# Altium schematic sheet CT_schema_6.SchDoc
size 274 x 160 mm
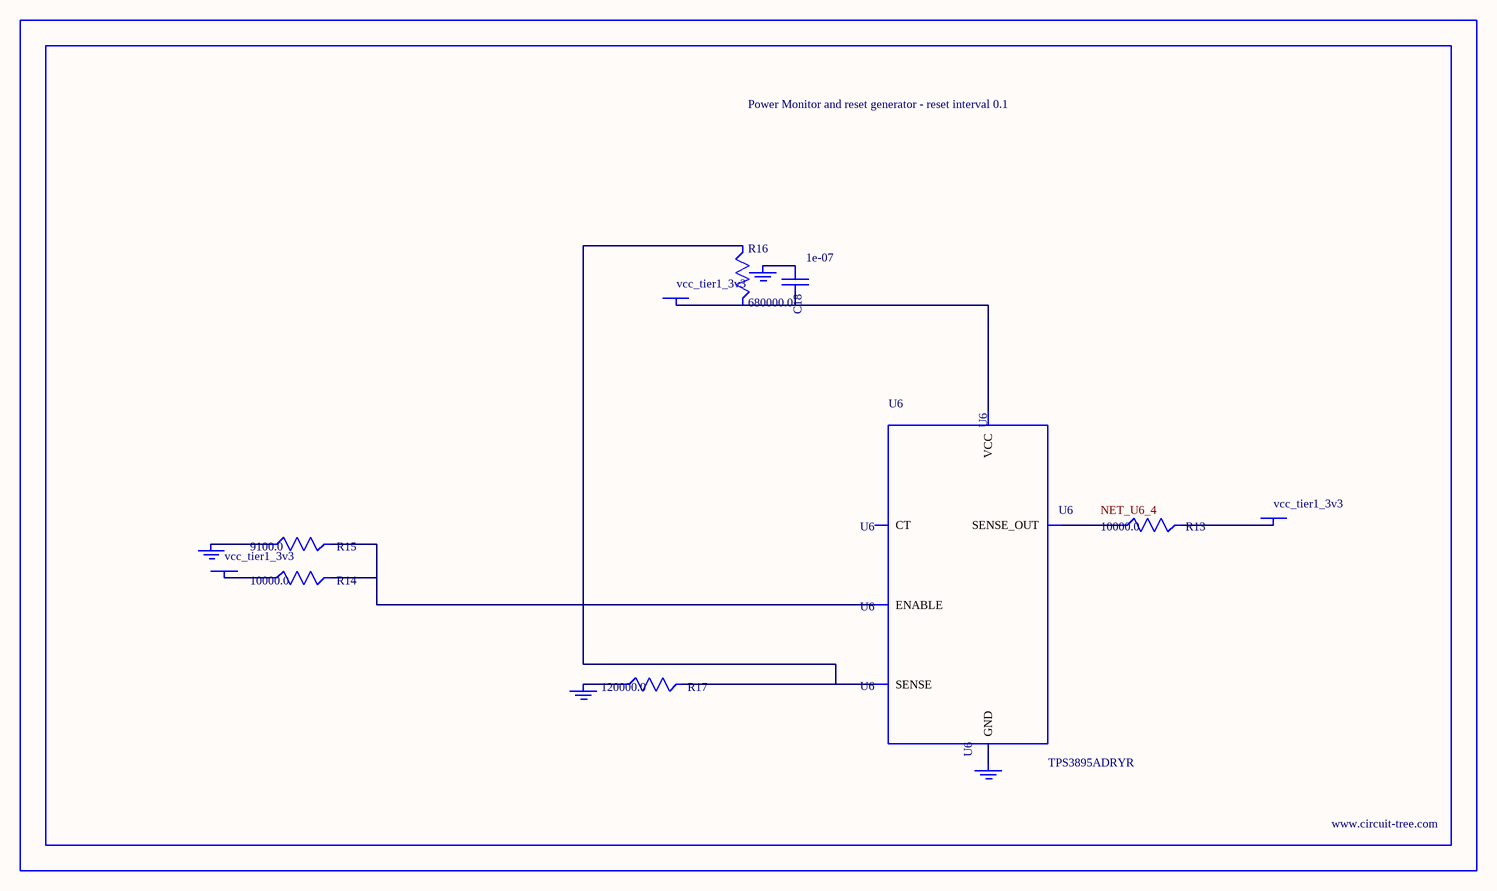
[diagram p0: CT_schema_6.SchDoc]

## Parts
BORDER5  (no value)
C18  1e-07  [C0402]
GND_INSTANCE_5_0  (no value)
GND_INSTANCE_5_1  (no value)
GND_INSTANCE_5_2  (no value)
GND_INSTANCE_5_3  (no value)
POWER_INSTANCE_5_0  vcc_tier1_3v3
POWER_INSTANCE_5_1  vcc_tier1_3v3
POWER_INSTANCE_5_2  vcc_tier1_3v3
R13  10000.0  [R0603]
R14  10000.0  [R0603]
R15  9100.0  [R0603]
R16  680000.0  [R0603]
R17  120000.0  [R0603]
U6  TPS3895ADRYR  [SON-6]

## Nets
NetC18_1: C18.1 GND_INSTANCE_5_2.0(GND)
NetC18_2: C18.2 POWER_INSTANCE_5_2.0(PWR) R16.2 U6.6(VCC)
NetGND_INSTANCE_5_0_0: GND_INSTANCE_5_0.0(GND) R15.1
NetGND_INSTANCE_5_1_0: GND_INSTANCE_5_1.0(GND) R17.1
NetGND_INSTANCE_5_3_0: GND_INSTANCE_5_3.0(GND) U6.2(GND)
NetPOWER_INSTANCE_5_0_0: POWER_INSTANCE_5_0.0(PWR) R14.1
NetPOWER_INSTANCE_5_1_0: POWER_INSTANCE_5_1.0(PWR) R13.2
NetR13_1: R13.1 U6.4(SENSE_OUT)
NetR14_2: R14.2 R15.2 U6.1(ENABLE)
NetR16_1: R16.1 R17.2 U6.3(SENSE)

Not connected (* = marked no-connect by the designer): U6 5(CT)

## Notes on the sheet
- Labels drawn without touching a wire or pin: NET_U6_4

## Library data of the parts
BORDER5 = BORDER_PAGE5
C18 = C0402C104K3RACTU
GND_INSTANCE_5_0-GND_INSTANCE_5_3 = GND
POWER_INSTANCE_5_0-POWER_INSTANCE_5_2 = PWR
R13 R14 = RC0603JR-0710KL
R15 = RC0603JR-079K1L
R16 = RC0603JR-07680KL
R17 = RC0603JR-07120KL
